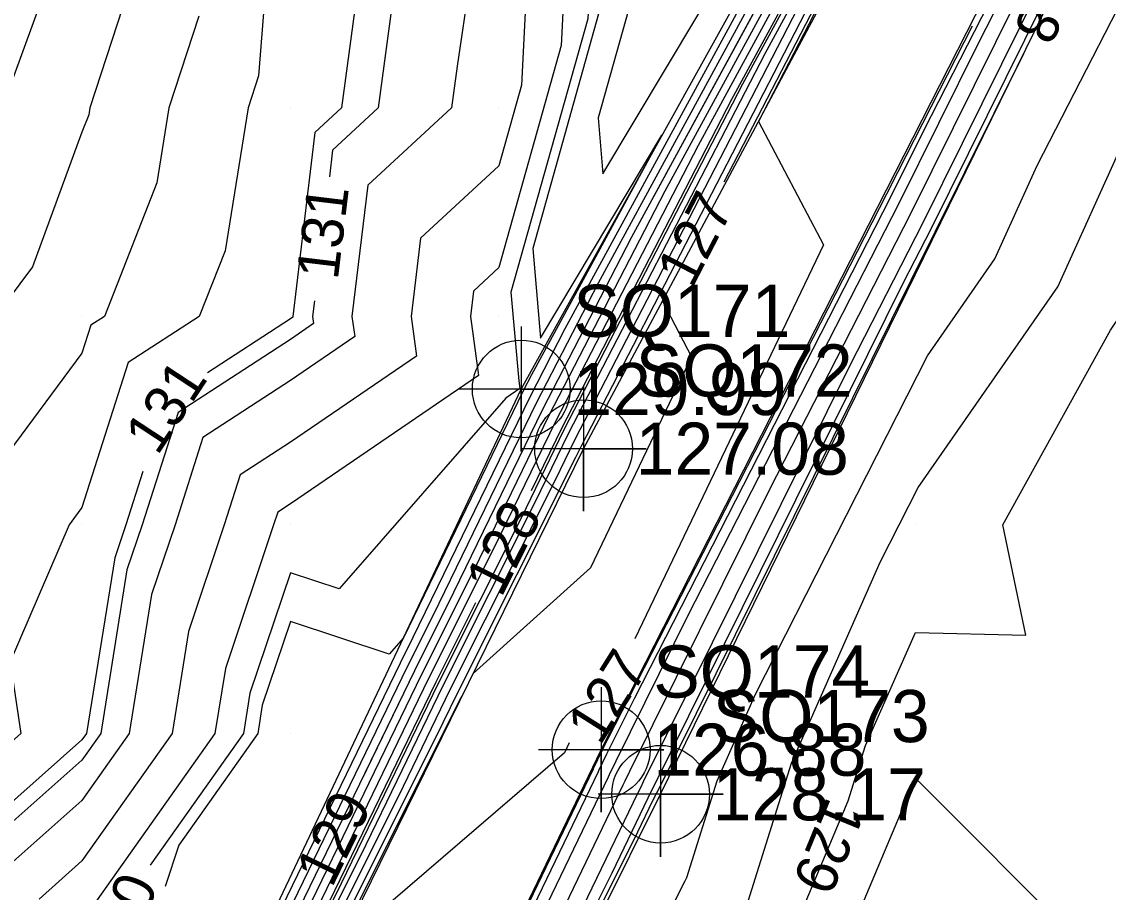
# Model space of a CAD drawing. Extents: x 2354170 to 2357230, y 866100 to 868290.
# Drawn here: x 2355367.1 to 2355419.2, y 866162.4 to 866204.1 of the extents above; entities that cross this region are included whole.
import ezdxf

# ---------------------------------------------------------------- set-up
doc = ezdxf.new("R2010")
doc.units = 0
for name, color, linetype in [('Default', 7, 'Continuous'), ('DTM Contours Major', 7, 'Continuous'), ('DTM Contours Major Text', 7, 'Continuous'), ('DTM Contours Minor', 7, 'Continuous'), ('DTM Contours Minor Text', 7, 'Continuous'), ('Exist DTM Breakline', 7, 'Continuous'), ('Exist DTM Breakline Cogo Elevation', 7, 'Continuous'), ('Exist DTM Breakline Cogo Number', 7, 'Continuous'), ('Exist DTM Breakline Cogo Point CELL', 7, 'Continuous'), ('Exist DTM QL2 LIDAR Elevation Point', 7, 'Continuous'), ('Exist DTM Ridgeline', 7, 'Continuous'), ('Exist DTM Ridgeline Cogo Elevation', 7, 'Continuous'), ('Exist DTM Ridgeline Cogo Number', 7, 'Continuous'), ('Exist DTM Ridgeline Cogo Point CELL', 7, 'Continuous')]:
    doc.layers.add(name, color=color, linetype=linetype)

msp = doc.modelspace()

# ---------------------------------------------------------------- linework, layer by layer
at = {"layer": 'Default'}
for points in [[(2355369.003, 866113.966), (2355372.331, 866120.627), (2355382.117, 866140.947), (2355385.48, 866147.675), (2355395.233, 866167.927), (2355395.282, 866168.026), (2355395.601, 866168.688), (2355399.083, 866175.702), (2355409.177, 866195.423), (2355412.985, 866203.103), (2355422.737, 866222.166), (2355426.373, 866229.511), (2355434.723, 866245.841), (2355439.532, 866253.514), (2355450.707, 866271.254), (2355454.96, 866278.038), (2355466.694, 866296.664)], [(2355370.068, 866113.383), (2355379.529, 866132.319), (2355383.361, 866140.276), (2355392.925, 866159.412), (2355396.659, 866167.165), (2355396.799, 866167.446), (2355396.921, 866167.699), (2355406.832, 866187.664), (2355410.335, 866194.507), (2355420.73, 866215.475), (2355423.723, 866221.327), (2355433.278, 866240.627), (2355435.51, 866244.994), (2355447.758, 866264.533), (2355451.475, 866270.433), (2355462.901, 866288.656)], [(2355392.805, 866150.86), (2355398.911, 866162.931), (2355398.997, 866163.101), (2355400.448, 866167.731), (2355402.291, 866171.889), (2355410.539, 866188.105), (2355413.781, 866192.76), (2355415.801, 866197.235), (2355421.733, 866208.801), (2355426.761, 866216.056), (2355426.756, 866220.53), (2355433.771, 866226.452), (2355438.466, 866235.311), (2355437.928, 866242.298), (2355442.074, 866247.038), (2355451.132, 866262.306), (2355455.703, 866265.278), (2355455.076, 866270.016), (2355461.998, 866275.608), (2355468.911, 866287.949)], [(2355446.099, 866283.993), (2355432.214, 866261.443), (2355430.808, 866260.964), (2355429.646, 866258.776), (2355428.035, 866256.274), (2355420.147, 866239.195), (2355420.045, 866239), (2355420.049, 866238.901), (2355419.563, 866237.931), (2355406.57, 866214.133), (2355405.767, 866212.586), (2355393.146, 866189.4), (2355391.457, 866186.133), (2355385.856, 866174.599), (2355385.239, 866173.372), (2355372.544, 866147.2), (2355372.141, 866146.396), (2355367.159, 866136.098), (2355359.577, 866124.423), (2355358.374, 866120.3), (2355358.114, 866120.108), (2355358.016, 866120.074), (2355357.865, 866120.141)], [(2355447.34, 866283.949), (2355443.3, 866277.611), (2355431.618, 866258.376), (2355423.711, 866243.925), (2355420.774, 866238.298), (2355411.101, 866220.58), (2355406.538, 866211.797), (2355397.939, 866195.999), (2355392.382, 866185.248), (2355388.783, 866177.837), (2355386.265, 866172.826), (2355377.95, 866155.685), (2355373.048, 866145.907), (2355363.734, 866126.654), (2355359.887, 866118.962)], [(2355447.631, 866283.829), (2355442.124, 866275.189), (2355431.857, 866258.285), (2355424.908, 866245.585), (2355420.984, 866238.065), (2355412.611, 866222.728), (2355406.796, 866211.535), (2355399.536, 866198.198), (2355392.69, 866184.953), (2355389.758, 866178.916), (2355386.606, 866172.644), (2355379.752, 866158.513), (2355373.351, 866145.744), (2355365.497, 866129.51), (2355360.15, 866118.818)], [(2355448.213, 866283.589), (2355439.772, 866270.346), (2355432.336, 866258.102), (2355427.303, 866248.904), (2355421.403, 866237.599), (2355415.631, 866227.026), (2355407.31, 866211.009), (2355402.732, 866202.597), (2355393.306, 866184.363), (2355391.709, 866181.074), (2355387.29, 866172.28), (2355383.355, 866164.169), (2355373.955, 866145.418), (2355369.022, 866135.222), (2355360.676, 866118.529)], [(2355448.504, 866283.469), (2355438.597, 866267.924), (2355432.576, 866258.011), (2355428.501, 866250.564), (2355421.613, 866237.366), (2355417.141, 866229.175), (2355407.568, 866210.746), (2355404.329, 866204.797), (2355393.615, 866184.068), (2355392.685, 866182.153), (2355387.632, 866172.098), (2355385.157, 866166.997), (2355374.258, 866145.255), (2355370.785, 866138.077), (2355360.938, 866118.385)], [(2355448.796, 866283.35), (2355437.421, 866265.502), (2355432.816, 866257.92), (2355429.699, 866252.224), (2355421.823, 866237.133), (2355418.651, 866231.324), (2355407.825, 866210.483), (2355405.927, 866206.996), (2355393.923, 866183.773), (2355393.66, 866183.233), (2355387.973, 866171.916), (2355386.959, 866169.826), (2355374.56, 866145.092), (2355372.548, 866140.933), (2355361.201, 866118.241)], [(2355369.535, 866113.675), (2355375.93, 866126.473), (2355382.739, 866140.611), (2355389.203, 866153.543), (2355395.946, 866167.546), (2355396.041, 866167.736), (2355396.261, 866168.193), (2355402.957, 866181.683), (2355409.756, 866194.965), (2355416.857, 866209.289), (2355423.23, 866221.746), (2355429.825, 866235.069), (2355435.116, 866245.417), (2355443.645, 866259.023), (2355451.091, 866270.844), (2355458.931, 866283.347)], [(2355445.652, 866282.454), (2355431.138, 866258.558), (2355421.315, 866240.605), (2355420.354, 866238.763), (2355408.08, 866216.282), (2355406.024, 866212.323), (2355394.743, 866191.6), (2355391.765, 866185.838), (2355386.832, 866175.679), (2355385.581, 866173.19), (2355374.346, 866150.028), (2355372.444, 866146.233), (2355360.208, 866120.943), (2355359.361, 866119.25)], [(2355401.938, 866161.963), (2355404.011, 866168.58), (2355408.279, 866178.209), (2355410.1, 866181.791), (2355416.803, 866191.414), (2355419.976, 866198.445), (2355421.203, 866198.774), (2355421.347, 866200.001), (2355423.369, 866203.394), (2355429.097, 866211.658), (2355429.085, 866220.148), (2355435.744, 866225.769), (2355439.976, 866227.75), (2355442.402, 866227.576), (2355443.042, 866230.002), (2355439.976, 866235.588), (2355439.605, 866240.418), (2355447.015, 866248.891), (2355450.41, 866254.613), (2355459.535, 866260.547), (2355458.285, 866270.007), (2355467.124, 866277.149)], [(2355439.033, 866269.613), (2355432.097, 866258.194), (2355426.106, 866247.244), (2355421.193, 866237.832), (2355414.121, 866224.877), (2355407.053, 866211.272), (2355401.134, 866200.398), (2355392.998, 866184.658), (2355391.534, 866181.644)], [(2355436.355, 866263.253), (2355436.245, 866263.081), (2355433.055, 866257.829), (2355430.896, 866253.884), (2355422.033, 866236.9), (2355420.161, 866233.473), (2355408.082, 866210.22), (2355407.524, 866209.196), (2355402.434, 866199.347), (2355405.549, 866193.436), (2355396.496, 866174.539)], [(2355419.976, 866252.553), (2355418.631, 866251.347), (2355418.257, 866250.002), (2355415.002, 866245.027), (2355412.258, 866239.775), (2355412.595, 866232.316), (2355408.485, 866224.121), (2355401.41, 866221.436), (2355399.976, 866220.714), (2355399.73, 866220.248), (2355399.606, 866220.001), (2355399.377, 866219.403), (2355393.325, 866210.001), (2355392.97, 866202.995), (2355389.976, 866192.345), (2355388.759, 866191.218), (2355388.611, 866190.001), (2355389.004, 866187.163), (2355379.976, 866181.007), (2355379.366, 866180.611), (2355379.171, 866180.001), (2355376.856, 866173.121), (2355376.354, 866170.001), (2355369.976, 866160.984)], [(2355407.913, 866218.846), (2355406.362, 866215.754), (2355403.976, 866214.848), (2355399.976, 866217.518), (2355395.137, 866210.001), (2355394.878, 866204.904), (2355391.605, 866193.258), (2355391.981, 866188.961), (2355397.8, 866198.685), (2355391.548, 866187.201), (2355391.149, 866186.428), (2355385.399, 866174.587), (2355384.713, 866173.803), (2355379.976, 866175.364), (2355378.625, 866171.351), (2355378.408, 866170.001), (2355374.619, 866164.644), (2355373.965, 866162.659)], [(2355375.496, 866218.337), (2355374.387, 866215.59), (2355372.933, 866210.001), (2355372.715, 866207.262), (2355370.356, 866200.001), (2355370.303, 866199.674), (2355369.976, 866198.841), (2355367.605, 866192.372), (2355365.804, 866190.001), (2355363.328, 866186.648), (2355359.976, 866182.144), (2355359.288, 866180.689), (2355358.976, 866180.001), (2355359.976, 866173.581), (2355360.506, 866170.001), (2355360.225, 866169.752), (2355359.976, 866169.347), (2355353.86, 866166.116), (2355350.538, 866160.001)], [(2355404.041, 866211.991), (2355399.976, 866214.704), (2355396.948, 866210.001), (2355396.787, 866206.812), (2355394.738, 866199.526), (2355394.974, 866196.838), (2355404.041, 866211.991)], [(2355379.117, 866210.001), (2355378.446, 866201.531), (2355377.948, 866200.001), (2355376.839, 866193.138), (2355375.607, 866190.001), (2355372.194, 866187.783), (2355369.976, 866180.834), (2355369.622, 866180.355), (2355369.358, 866180.001), (2355366.539, 866173.438), (2355367.048, 866170.001), (2355363.302, 866166.675), (2355359.976, 866161.282)], [(2355389.167, 866210.001), (2355387.974, 866202.003), (2355387.703, 866200.001), (2355383.691, 866196.286), (2355382.93, 866190.001), (2355383.064, 866189.03), (2355379.976, 866186.924), (2355375.78, 866184.197), (2355374.44, 866180.001), (2355373.316, 866176.661), (2355372.245, 866170.001), (2355369.976, 866166.792), (2355366.378, 866163.598), (2355364.16, 866160.001)], [(2355391.513, 866210.001), (2355391.061, 866201.087), (2355389.976, 866197.225), (2355386.225, 866193.752), (2355385.771, 866190.001), (2355386.034, 866188.097), (2355379.976, 866183.966), (2355377.573, 866182.404), (2355376.806, 866180.001), (2355375.086, 866174.891), (2355374.3, 866170.001), (2355369.976, 866163.888), (2355367.917, 866162.06)], [(2355369.683, 866209.709), (2355366.153, 866200.001), (2355364.497, 866195.48), (2355360.334, 866190.001), (2355360.182, 866189.795), (2355359.976, 866189.518), (2355356.92, 866183.056), (2355355.537, 866180.001), (2355356.563, 866173.414), (2355353.58, 866170.001), (2355351.222, 866168.755), (2355349.975, 866166.46), (2355347.71, 866162.266)], [(2355404.413, 866208.628), (2355396.341, 866193.799), (2355392.073, 866185.543), (2355387.807, 866176.758), (2355385.923, 866173.008), (2355376.148, 866152.856), (2355372.746, 866146.07), (2355361.971, 866123.798), (2355359.624, 866119.106)], [(2355383.33, 866206.647), (2355382.432, 866200.001), (2355381.156, 866198.82), (2355380.089, 866190.001), (2355380.095, 866189.964), (2355379.976, 866189.883), (2355376.003, 866187.3)], [(2355375.58, 866204.396), (2355374.152, 866200.001), (2355373.571, 866196.406), (2355371.056, 866190.001), (2355370.401, 866189.576), (2355369.976, 866188.243), (2355366.475, 866183.502), (2355363.869, 866180.001), (2355362.699, 866177.277), (2355363.777, 866170.001), (2355361.763, 866168.213), (2355359.976, 866165.314), (2355356.499, 866163.477), (2355354.61, 866160.001)], [(2355368.471, 866114.258), (2355368.733, 866114.781), (2355381.496, 866141.283), (2355381.757, 866141.806), (2355394.52, 866168.308), (2355394.524, 866168.316), (2355394.941, 866169.182), (2355395.209, 866169.721), (2355408.599, 866195.88), (2355409.113, 866196.917), (2355412.703, 866203.936)], [(2355370.6, 866113.091), (2355383.127, 866138.165), (2355383.982, 866139.94), (2355396.648, 866165.28), (2355397.372, 866166.784), (2355397.558, 866167.156), (2355397.582, 866167.205), (2355410.706, 866193.644), (2355410.914, 866194.05), (2355415.159, 866202.614)], [(2355406.916, 866167.329), (2355407.574, 866169.429), (2355409.976, 866174.848), (2355415.269, 866174.708), (2355414.161, 866180.001), (2355419.322, 866189.347), (2355419.825, 866190.069)], [(2355372.893, 866182.565), (2355372.075, 866180.001), (2355371.546, 866178.43), (2355370.191, 866170.001), (2355369.976, 866169.696), (2355364.84, 866165.136), (2355361.673, 866160.001), (2355360.954, 866159.022), (2355359.976, 866154.612), (2355358.407, 866151.57), (2355357.688, 866150.001), (2355353.382, 866146.593), (2355350.654, 866140), (2355350.554, 866139.422), (2355349.975, 866136.97), (2355347.996, 866131.98), (2355348.093, 866130.941), (2355345.494, 866129.03), (2355344.276, 866128.597), (2355342.39, 866129.443)], [(2355388.863, 866176.272), (2355386.948, 866172.462), (2355381.554, 866161.341), (2355373.653, 866145.581), (2355367.26, 866132.366), (2355360.413, 866118.674)], [(2355393.346, 866169.545), (2355393.121, 866169.079), (2355382.291, 866159.747), (2355374.862, 866144.929), (2355374.311, 866143.789), (2355361.464, 866118.097)], [(2355406.659, 866160.001), (2355409.976, 866167.859), (2355417.825, 866160.001), (2355416.08, 866153.897), (2355409.976, 866156.046), (2355406.659, 866160.001)]]:
    msp.add_lwpolyline(points, dxfattribs=at)
at = {"layer": 'DTM Contours Major'}
msp.add_lwpolyline([(2355416.676, 866243.006), (2355414.854, 866239.517), (2355415.08, 866234.511), (2355407.07, 866218.543), (2355402.465, 866216.795), (2355399.976, 866218.456), (2355394.533, 866210.001), (2355394.242, 866204.267), (2355390.56, 866191.169), (2355390.933, 866186.906), (2355390.984, 866186.541), (2355390.314, 866186.084), (2355382.32, 866176.934), (2355379.976, 866177.707), (2355378.035, 866171.941), (2355377.723, 866170.001), (2355373.253, 866163.681)], dxfattribs=at)
at = {"layer": 'DTM Contours Minor'}
for points in [[(2355507.624, 866364.327), (2355498.127, 866350.2), (2355482.831, 866336.367), (2355481.409, 866334.166), (2355481.276, 866333.947), (2355466.529, 866311.006), (2355465.085, 866308.635), (2355451.603, 866287.566), (2355448.99, 866283.27), (2355436.637, 866263.888), (2355432.975, 866257.86), (2355430.497, 866253.331), (2355421.963, 866236.978), (2355419.658, 866232.756), (2355407.996, 866210.308), (2355406.992, 866208.462), (2355400.777, 866196.439)], [(2355482.306, 866341.407), (2355478.52, 866335.199), (2355474.721, 866329.289), (2355462.76, 866309.647), (2355459.609, 866304.723), (2355447.048, 866284.069), (2355444.476, 866280.032), (2355431.378, 866258.467), (2355422.513, 866242.265), (2355420.564, 866238.53), (2355409.591, 866218.431), (2355406.281, 866212.06), (2355396.341, 866193.799), (2355392.073, 866185.543), (2355387.807, 866176.758), (2355385.923, 866173.008), (2355383.365, 866167.736)], [(2355368.648, 866114.161), (2355369.932, 866116.73), (2355381.703, 866141.171), (2355382.998, 866143.762), (2355394.758, 866168.181), (2355394.777, 866168.219), (2355395.161, 866169.017), (2355396.5, 866171.715), (2355408.792, 866195.728), (2355410.403, 866198.979), (2355422.408, 866222.445), (2355424.071, 866225.805), (2355434.46, 866246.123), (2355436.79, 866249.841), (2355450.451, 866271.528), (2355452.314, 866274.499), (2355462.442, 866290.577)], [(2355370.422, 866113.188), (2355381.928, 866136.216), (2355383.775, 866140.052), (2355395.407, 866163.324), (2355397.135, 866166.911), (2355397.305, 866167.252), (2355397.362, 866167.369), (2355409.415, 866191.651), (2355410.721, 866194.202), (2355423.311, 866219.599), (2355424.052, 866221.048), (2355435.579, 866244.333), (2355435.773, 866244.712), (2355450.5, 866268.206), (2355451.731, 866270.16), (2355464.001, 866289.728)], [(2355426.861, 866280.002), (2355423.138, 866276.841), (2355421.228, 866270.002), (2355419.976, 866267.195), (2355416.625, 866263.353), (2355415.205, 866260.002), (2355412.448, 866257.53), (2355410.353, 866250.002), (2355409.976, 866249.425), (2355405.066, 866244.912), (2355402.782, 866240.002), (2355402.9, 866237.078), (2355399.976, 866235.83), (2355397.349, 866232.628), (2355396.35, 866230.002), (2355394.148, 866225.829), (2355391.225, 866220.001), (2355389.976, 866216.731), (2355387.29, 866212.687), (2355385.609, 866210.001), (2355384.878, 866205.099), (2355384.189, 866200.001), (2355382.001, 866197.976), (2355381.847, 866196.701)], [(2355410.096, 866216.877), (2355407.139, 866211.184), (2355401.666, 866201.131), (2355393.101, 866184.56), (2355391.059, 866180.355), (2355387.062, 866172.402), (2355382.154, 866162.284), (2355373.754, 866145.527), (2355367.847, 866133.318), (2355360.5, 866118.625)], [(2355372.715, 866207.262), (2355370.356, 866200.001), (2355370.303, 866199.674), (2355369.976, 866198.841), (2355367.605, 866192.372), (2355365.804, 866190.001), (2355363.328, 866186.648), (2355359.976, 866182.144), (2355359.288, 866180.689), (2355358.976, 866180.001), (2355359.976, 866173.581), (2355360.506, 866170.001), (2355360.225, 866169.752), (2355359.976, 866169.347), (2355353.86, 866166.116), (2355350.538, 866160.001)], [(2355398.022, 866191.109), (2355397.824, 866190.726), (2355399.227, 866188.063), (2355394.378, 866177.939), (2355388.749, 866172.884), (2355388.201, 866171.795), (2355388.161, 866171.711), (2355374.762, 866144.983), (2355373.723, 866142.837), (2355361.376, 866118.145)], [(2355381.126, 866190.745), (2355381.036, 866190.001), (2355381.085, 866189.653), (2355379.976, 866188.897), (2355374.585, 866185.392), (2355372.863, 866180.001), (2355372.136, 866177.84), (2355370.876, 866170.001), (2355369.976, 866168.728), (2355365.353, 866164.624), (2355362.502, 866160.001), (2355361.432, 866158.544), (2355359.976, 866151.98), (2355359.302, 866150.674), (2355358.994, 866150.001), (2355353.959, 866146.017), (2355351.47, 866140), (2355351.248, 866138.728), (2355349.975, 866133.333), (2355349.029, 866130.947), (2355349.076, 866130.45), (2355346.335, 866128.435), (2355345.192, 866128.029), (2355343.422, 866128.823)], [(2355404.636, 866161.782), (2355406.74, 866166.764), (2355407.574, 866169.429), (2355409.976, 866174.848), (2355415.269, 866174.708), (2355414.161, 866180.001), (2355419.322, 866189.347), (2355419.825, 866190.069)]]:
    msp.add_lwpolyline(points, dxfattribs=at)
at = {"layer": 'Exist DTM Breakline'}
for points in [[(2355361.743, 866117.945), (2355394.044, 866183.657), (2355433.595, 866257.624), (2355503.452, 866369.345), (2355596.389, 866487.309), (2355657.482, 866552.264), (2355736.192, 866624.67), (2355827.155, 866697.764), (2355869.568, 866728.835), (2355917.569, 866765.212), (2355965.057, 866802.758)], [(2355368.426, 866114.283), (2355394.886, 866169.223), (2355434.213, 866246.388), (2355517.974, 866378.796), (2355601.384, 866486.265), (2355669.136, 866558.092), (2355738.686, 866620.007), (2355814.815, 866681.573), (2355823.796, 866686.804), (2355859.089, 866669.853), (2355910.743, 866643.967)]]:
    msp.add_lwpolyline(points, dxfattribs=at)
at = {"layer": 'Exist DTM Breakline Cogo Point CELL'}
for points in [[(2355394.044, 866186.657), (2355394.044, 866180.657), (2355394.044, 866183.657), (2355397.044, 866183.657), (2355391.044, 866183.657)], [(2355394.886, 866172.223), (2355394.886, 866166.223), (2355394.886, 866169.223), (2355397.886, 866169.223), (2355391.886, 866169.223)]]:
    msp.add_lwpolyline(points, dxfattribs=at)
for centre in [(2355394.044, 866183.657), (2355394.886, 866169.223)]:
    msp.add_circle(centre, 2.344, dxfattribs=at)
at = {"layer": 'Exist DTM QL2 LIDAR Elevation Point'}
for p, q in [((2355369.976, 866200.001), (2355369.976, 866200.001)), ((2355379.976, 866200.001), (2355379.976, 866200.001)), ((2355389.976, 866200.001), (2355389.976, 866200.001)), ((2355369.976, 866190.001), (2355369.976, 866190.001)), ((2355379.976, 866190.001), (2355379.976, 866190.001)), ((2355389.976, 866190.001), (2355389.976, 866190.001)), ((2355369.976, 866180.001), (2355369.976, 866180.001)), ((2355379.976, 866180.001), (2355379.976, 866180.001)), ((2355409.976, 866180.001), (2355409.976, 866180.001)), ((2355369.976, 866170.001), (2355369.976, 866170.001)), ((2355379.976, 866170.001), (2355379.976, 866170.001)), ((2355409.976, 866170.001), (2355409.976, 866170.001))]:
    msp.add_line(p, q, dxfattribs=at)
at = {"layer": 'Exist DTM Ridgeline'}
for points in [[(2355359.213, 866119.331), (2355391.053, 866186.519), (2355431.025, 866258.601), (2355499.325, 866371.654), (2355593.685, 866489.44), (2355651.917, 866551.384), (2355734.914, 866627.002), (2355826.445, 866700.139), (2355852.871, 866722.788), (2355915.412, 866769.543), (2355965.686, 866805.255), (2355970.961, 866806.36)], [(2355370.777, 866112.994), (2355397.74, 866167.086), (2355435.798, 866244.685), (2355518.891, 866375.793), (2355604.418, 866484.066), (2355673.042, 866557.712), (2355740.701, 866618.519), (2355815.663, 866679.47), (2355822.993, 866684.568), (2355856.949, 866667.182), (2355908.264, 866642.016)]]:
    msp.add_lwpolyline(points, dxfattribs=at)
at = {"layer": 'Exist DTM Ridgeline Cogo Point CELL'}
for points in [[(2355391.053, 866189.519), (2355391.053, 866183.519), (2355391.053, 866186.519), (2355394.053, 866186.519), (2355388.053, 866186.519)], [(2355397.74, 866170.086), (2355397.74, 866164.086), (2355397.74, 866167.086), (2355400.74, 866167.086), (2355394.74, 866167.086)]]:
    msp.add_lwpolyline(points, dxfattribs=at)
for centre in [(2355391.053, 866186.519), (2355397.74, 866167.086)]:
    msp.add_circle(centre, 2.344, dxfattribs=at)

# ---------------------------------------------------------------- texts
at = {"layer": 'Default'}
for s, rotation, p in [('128', 242.9907, (2355416.658, 866207.772)), ('131', 56.7077, (2355373.596, 866183.281)), ('128', 63.5564, (2355390.092, 866176.47)), ('127', 57.7551, (2355394.831, 866169.375)), ('129', 247.653, (2355405.743, 866167.03))]:
    msp.add_text(s, height=2, rotation=rotation, dxfattribs=at).set_placement(p)
at = {"layer": 'DTM Contours Major Text'}
msp.add_text('130', height=2, rotation=66.9951, dxfattribs=at).set_placement((2355371.912, 866158.6))
at = {"layer": 'DTM Contours Minor Text'}
for s, rotation, p in [('131', 83.1013, (2355382.25, 866191.711)), ('127', 62.6657, (2355399.243, 866191.293)), ('129', 64.1236, (2355381.963, 866162.553))]:
    msp.add_text(s, height=2, rotation=rotation, dxfattribs=at).set_placement(p)
at = {"layer": 'Exist DTM Breakline Cogo Elevation'}
for s, p in [('127.08', (2355396.544, 866182.407)), ('126.88', (2355397.386, 866167.973))]:
    msp.add_text(s, height=2.5, dxfattribs=at).set_placement(p)
at = {"layer": 'Exist DTM Breakline Cogo Number'}
for s, p in [('SQ172', (2355396.544, 866186.157)), ('SQ174', (2355397.386, 866171.723))]:
    msp.add_text(s, height=2.5, dxfattribs=at).set_placement(p)
at = {"layer": 'Exist DTM Ridgeline Cogo Elevation'}
for s, p in [('129.99', (2355393.553, 866185.269)), ('128.17', (2355400.24, 866165.836))]:
    msp.add_text(s, height=2.5, dxfattribs=at).set_placement(p)
at = {"layer": 'Exist DTM Ridgeline Cogo Number'}
for s, p in [('SQ171', (2355393.553, 866189.019)), ('SQ173', (2355400.24, 866169.586))]:
    msp.add_text(s, height=2.5, dxfattribs=at).set_placement(p)

doc.saveas('drawing.dxf')
